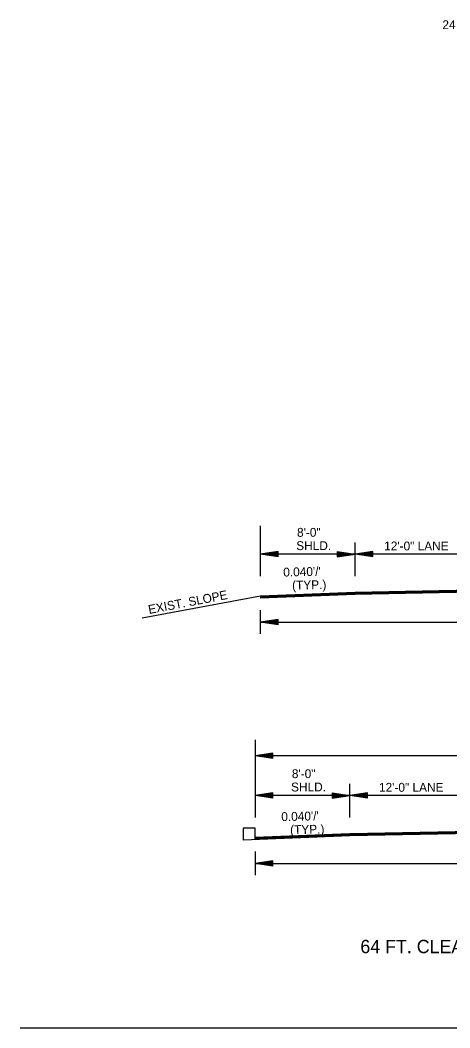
# Model space of a CAD drawing. Extents: x 544199 to 1930787, y -1968972 to 596640.
# Drawn here: x 546330 to 546693, y -1959492 to -1958641 of the extents above; entities that cross this region are included whole.
import ezdxf

# ---------------------------------------------------------------- set-up
doc = ezdxf.new("R2010")
doc.units = 0
doc.layers.add('R_Border', color=7, linetype='Continuous')
doc.layers.add('R_Draft', color=7, linetype='Continuous')

msp = doc.modelspace()

# ---------------------------------------------------------------- linework, layer by layer
at = {"layer": 'R_Border'}
for p, q in [((546612.65, -1959091.84), (546532.53, -1959091.84)), ((546612.65, -1959125.92), (546532.53, -1959129.12)), ((546612.65, -1959124.25), (546532.65, -1959127.45)), ((546612.65, -1959124.55), (546532.65, -1959127.75)), ((546612.65, -1959124.85), (546532.65, -1959128.05)), ((546612.65, -1959125.15), (546532.65, -1959128.35)), ((546612.65, -1959125.45), (546532.65, -1959128.65)), ((546612.65, -1959125.75), (546532.65, -1959128.95)), ((546608.29, -1959295.8), (546528.16, -1959295.8)), ((546528.29, -1959323.5), (546518.12, -1959323.5)), ((546518.12, -1959323.5), (546518.12, -1959333.48)), ((546528.29, -1959332.91), (546528.29, -1959323.5)), ((546608.29, -1959329.88), (546518.12, -1959333.48)), ((546608.29, -1959328.2), (546528.29, -1959331.4)), ((546608.29, -1959328.5), (546528.29, -1959331.7)), ((546608.29, -1959328.8), (546528.29, -1959332)), ((546608.29, -1959329.1), (546528.29, -1959332.3)), ((546608.29, -1959329.41), (546528.29, -1959332.61)), ((546608.29, -1959329.71), (546528.29, -1959332.91)), ((546329.55, -1959492.13), (547251.13, -1959492.13))]:
    msp.add_line(p, q, dxfattribs=at)
at = {"layer": 'R_Draft'}
for p, q in [((546532.53, -1959067.78), (546532.53, -1959110.5)), ((546612.65, -1959110.5), (546612.65, -1959081.95)), ((546547.53, -1959089.59), (546532.53, -1959091.84)), ((546547.53, -1959094.09), (546532.53, -1959091.84)), ((546547.53, -1959089.97), (546535.03, -1959091.84)), ((546547.53, -1959093.72), (546535.03, -1959091.84)), ((546547.53, -1959090.35), (546537.61, -1959091.84)), ((546547.53, -1959093.33), (546537.61, -1959091.84)), ((546547.53, -1959090.72), (546540.11, -1959091.84)), ((546547.53, -1959092.96), (546540.11, -1959091.84)), ((546547.53, -1959091.11), (546542.65, -1959091.84)), ((546547.53, -1959092.57), (546542.65, -1959091.84)), ((546547.53, -1959091.49), (546545.16, -1959091.84)), ((546547.53, -1959092.19), (546545.16, -1959091.84)), ((546547.53, -1959094.09), (546547.53, -1959089.59)), ((546597.65, -1959089.59), (546612.65, -1959091.84)), ((546597.65, -1959089.59), (546597.65, -1959094.09)), ((546597.65, -1959089.97), (546610.15, -1959091.84)), ((546597.65, -1959090.35), (546607.57, -1959091.84)), ((546597.65, -1959090.72), (546605.07, -1959091.84)), ((546597.65, -1959091.11), (546602.53, -1959091.84)), ((546597.65, -1959091.49), (546600.02, -1959091.84)), ((546597.65, -1959094.09), (546612.65, -1959091.84)), ((546597.65, -1959092.58), (546602.53, -1959091.84)), ((546597.65, -1959093.33), (546607.57, -1959091.84)), ((546597.65, -1959093.72), (546610.15, -1959091.84)), ((546597.65, -1959092.96), (546605.07, -1959091.84)), ((546597.65, -1959092.19), (546600.02, -1959091.84)), ((546627.65, -1959089.59), (546612.65, -1959091.84)), ((546732.65, -1959091.84), (546612.65, -1959091.84)), ((546627.65, -1959094.09), (546612.65, -1959091.84)), ((546627.65, -1959089.97), (546615.16, -1959091.84)), ((546627.65, -1959093.72), (546615.16, -1959091.84)), ((546627.65, -1959090.35), (546617.74, -1959091.84)), ((546627.65, -1959093.33), (546617.74, -1959091.84)), ((546627.65, -1959090.72), (546620.24, -1959091.84)), ((546627.65, -1959092.96), (546620.24, -1959091.84)), ((546627.65, -1959091.11), (546622.78, -1959091.84)), ((546627.65, -1959092.57), (546622.78, -1959091.84)), ((546627.65, -1959091.49), (546625.28, -1959091.84)), ((546627.65, -1959092.19), (546625.28, -1959091.84)), ((546627.65, -1959094.09), (546627.65, -1959089.59)), ((546852.65, -1959119.45), (546612.65, -1959124.25)), ((546852.66, -1959119.75), (546612.65, -1959124.55)), ((546852.67, -1959120.05), (546612.65, -1959124.85)), ((546852.67, -1959120.35), (546612.65, -1959125.15)), ((546532.65, -1959127.45), (546432.59, -1959145.82)), ((546852.68, -1959120.65), (546612.65, -1959125.45)), ((546852.68, -1959120.95), (546612.65, -1959125.75)), ((546852.69, -1959121.12), (546612.65, -1959125.92)), ((546532.53, -1959139.06), (546532.53, -1959159.06)), ((546547.53, -1959147.06), (546532.53, -1959149.31)), ((546532.53, -1959149.31), (547172.78, -1959149.31)), ((546547.53, -1959151.56), (546532.53, -1959149.31)), ((546547.53, -1959147.43), (546535.03, -1959149.31)), ((546547.53, -1959151.18), (546535.03, -1959149.31)), ((546547.53, -1959147.81), (546537.61, -1959149.31)), ((546547.53, -1959150.8), (546537.61, -1959149.31)), ((546547.53, -1959148.19), (546540.11, -1959149.31)), ((546547.53, -1959150.42), (546540.11, -1959149.31)), ((546547.53, -1959148.57), (546542.65, -1959149.31)), ((546547.53, -1959150.03), (546542.65, -1959149.31)), ((546547.53, -1959148.95), (546545.16, -1959149.31)), ((546547.53, -1959149.66), (546545.16, -1959149.31)), ((546547.53, -1959151.56), (546547.53, -1959147.06)), ((546528.16, -1959248.8), (546528.16, -1959314.46)), ((546543.16, -1959260.01), (546528.16, -1959262.26)), ((546543.16, -1959264.51), (546528.16, -1959262.26)), ((547168.41, -1959262.26), (546528.16, -1959262.26)), ((546543.16, -1959260.39), (546530.67, -1959262.26)), ((546543.16, -1959264.14), (546530.67, -1959262.26)), ((546543.16, -1959260.77), (546533.25, -1959262.26)), ((546543.16, -1959263.75), (546533.25, -1959262.26)), ((546543.16, -1959261.14), (546535.74, -1959262.26)), ((546543.16, -1959263.38), (546535.74, -1959262.26)), ((546543.16, -1959261.53), (546538.29, -1959262.26)), ((546543.16, -1959262.99), (546538.29, -1959262.26)), ((546543.16, -1959261.91), (546540.79, -1959262.26)), ((546543.16, -1959262.61), (546540.79, -1959262.26)), ((546543.16, -1959264.51), (546543.16, -1959260.01)), ((546608.29, -1959314.46), (546608.29, -1959285.91)), ((546543.16, -1959293.55), (546528.16, -1959295.8)), ((546543.16, -1959298.05), (546528.16, -1959295.8)), ((546543.16, -1959293.92), (546530.67, -1959295.8)), ((546543.16, -1959297.67), (546530.67, -1959295.8)), ((546543.16, -1959294.31), (546533.25, -1959295.8)), ((546543.16, -1959297.29), (546533.25, -1959295.8)), ((546543.16, -1959294.68), (546535.74, -1959295.8)), ((546543.16, -1959296.92), (546535.74, -1959295.8)), ((546543.16, -1959295.06), (546538.29, -1959295.8)), ((546543.16, -1959296.53), (546538.29, -1959295.8)), ((546543.16, -1959295.45), (546540.79, -1959295.8)), ((546543.16, -1959296.15), (546540.79, -1959295.8)), ((546543.16, -1959298.05), (546543.16, -1959293.55)), ((546593.29, -1959293.55), (546608.29, -1959295.8)), ((546593.29, -1959293.55), (546593.29, -1959298.05)), ((546593.29, -1959293.92), (546605.78, -1959295.8)), ((546593.29, -1959294.31), (546603.2, -1959295.8)), ((546593.29, -1959294.68), (546600.7, -1959295.8)), ((546593.29, -1959295.07), (546598.16, -1959295.8)), ((546593.29, -1959295.45), (546595.66, -1959295.8)), ((546593.29, -1959298.05), (546608.29, -1959295.8)), ((546593.29, -1959296.53), (546598.16, -1959295.8)), ((546593.29, -1959297.29), (546603.2, -1959295.8)), ((546593.29, -1959297.67), (546605.78, -1959295.8)), ((546593.29, -1959296.92), (546600.7, -1959295.8)), ((546593.29, -1959296.15), (546595.66, -1959295.8)), ((546623.29, -1959293.55), (546608.29, -1959295.8)), ((546728.29, -1959295.8), (546608.29, -1959295.8)), ((546623.29, -1959298.05), (546608.29, -1959295.8)), ((546623.29, -1959293.92), (546610.79, -1959295.8)), ((546623.29, -1959297.67), (546610.79, -1959295.8)), ((546623.29, -1959294.31), (546613.37, -1959295.8)), ((546623.29, -1959297.29), (546613.37, -1959295.8)), ((546623.29, -1959294.68), (546615.87, -1959295.8)), ((546623.29, -1959296.92), (546615.87, -1959295.8)), ((546623.29, -1959295.06), (546618.41, -1959295.8)), ((546623.29, -1959296.53), (546618.41, -1959295.8)), ((546623.29, -1959295.45), (546620.92, -1959295.8)), ((546623.29, -1959296.15), (546620.92, -1959295.8)), ((546623.29, -1959298.05), (546623.29, -1959293.55)), ((546848.29, -1959323.4), (546608.29, -1959328.2)), ((546848.29, -1959323.7), (546608.29, -1959328.5)), ((546848.3, -1959324), (546608.29, -1959328.8)), ((546848.31, -1959324.3), (546608.29, -1959329.1)), ((546848.31, -1959324.6), (546608.29, -1959329.41)), ((546848.32, -1959324.9), (546608.29, -1959329.71)), ((546848.32, -1959325.07), (546608.29, -1959329.88)), ((546528.16, -1959343.01), (546528.16, -1959363.01)), ((546543.16, -1959351.01), (546528.16, -1959353.26)), ((546528.16, -1959353.26), (547168.41, -1959353.26)), ((546543.16, -1959355.51), (546528.16, -1959353.26)), ((546543.16, -1959351.39), (546530.67, -1959353.26)), ((546543.16, -1959355.14), (546530.67, -1959353.26)), ((546543.16, -1959351.77), (546533.25, -1959353.26)), ((546543.16, -1959354.76), (546533.25, -1959353.26)), ((546543.16, -1959352.15), (546535.74, -1959353.26)), ((546543.16, -1959354.38), (546535.74, -1959353.26)), ((546543.16, -1959352.53), (546538.29, -1959353.26)), ((546543.16, -1959353.99), (546538.29, -1959353.26)), ((546543.16, -1959352.91), (546540.79, -1959353.26)), ((546543.16, -1959353.62), (546540.79, -1959353.26)), ((546543.16, -1959355.51), (546543.16, -1959351.01))]:
    msp.add_line(p, q, dxfattribs=at)

# ---------------------------------------------------------------- texts
for s, height, p in [('      24  - BR. NO. 06978 - HWY. 15', 7.5, (546669.74, -1958648.16)), ('8\'-0"', 7.5, (546563.59, -1959077.14)), ('SHLD.', 7.5, (546562.91, -1959088.39)), ('12\'-0" LANE', 7.5, (546637.23, -1959088.67)), ('8\'-0"', 7.5, (546559.22, -1959281.1)), ('SHLD.', 7.5, (546558.54, -1959292.35)), ('12\'-0" LANE', 7.5, (546632.86, -1959292.63)), ('64 FT. CLEAR ROADWAY BRIDGE - POLYMER OVERLAY', 11.25, (546617.14, -1959429.02))]:
    msp.add_text(s, height=height, dxfattribs=at).set_placement(p)
for s, rotation, p in [("0.040'/' ", 1.31838, (546552.03, -1959110.78)), ('(TYP.)', 1.31838, (546559.49, -1959121.86)), ('EXIST. SLOPE', 10.88286, (546438.57, -1959142.45)), ("0.040'/' ", 1.31838, (546550.36, -1959317.43)), ('(TYP.)', 1.31838, (546557.82, -1959328.51))]:
    msp.add_text(s, height=7.5, rotation=rotation, dxfattribs=at).set_placement(p)

doc.saveas('drawing.dxf')
